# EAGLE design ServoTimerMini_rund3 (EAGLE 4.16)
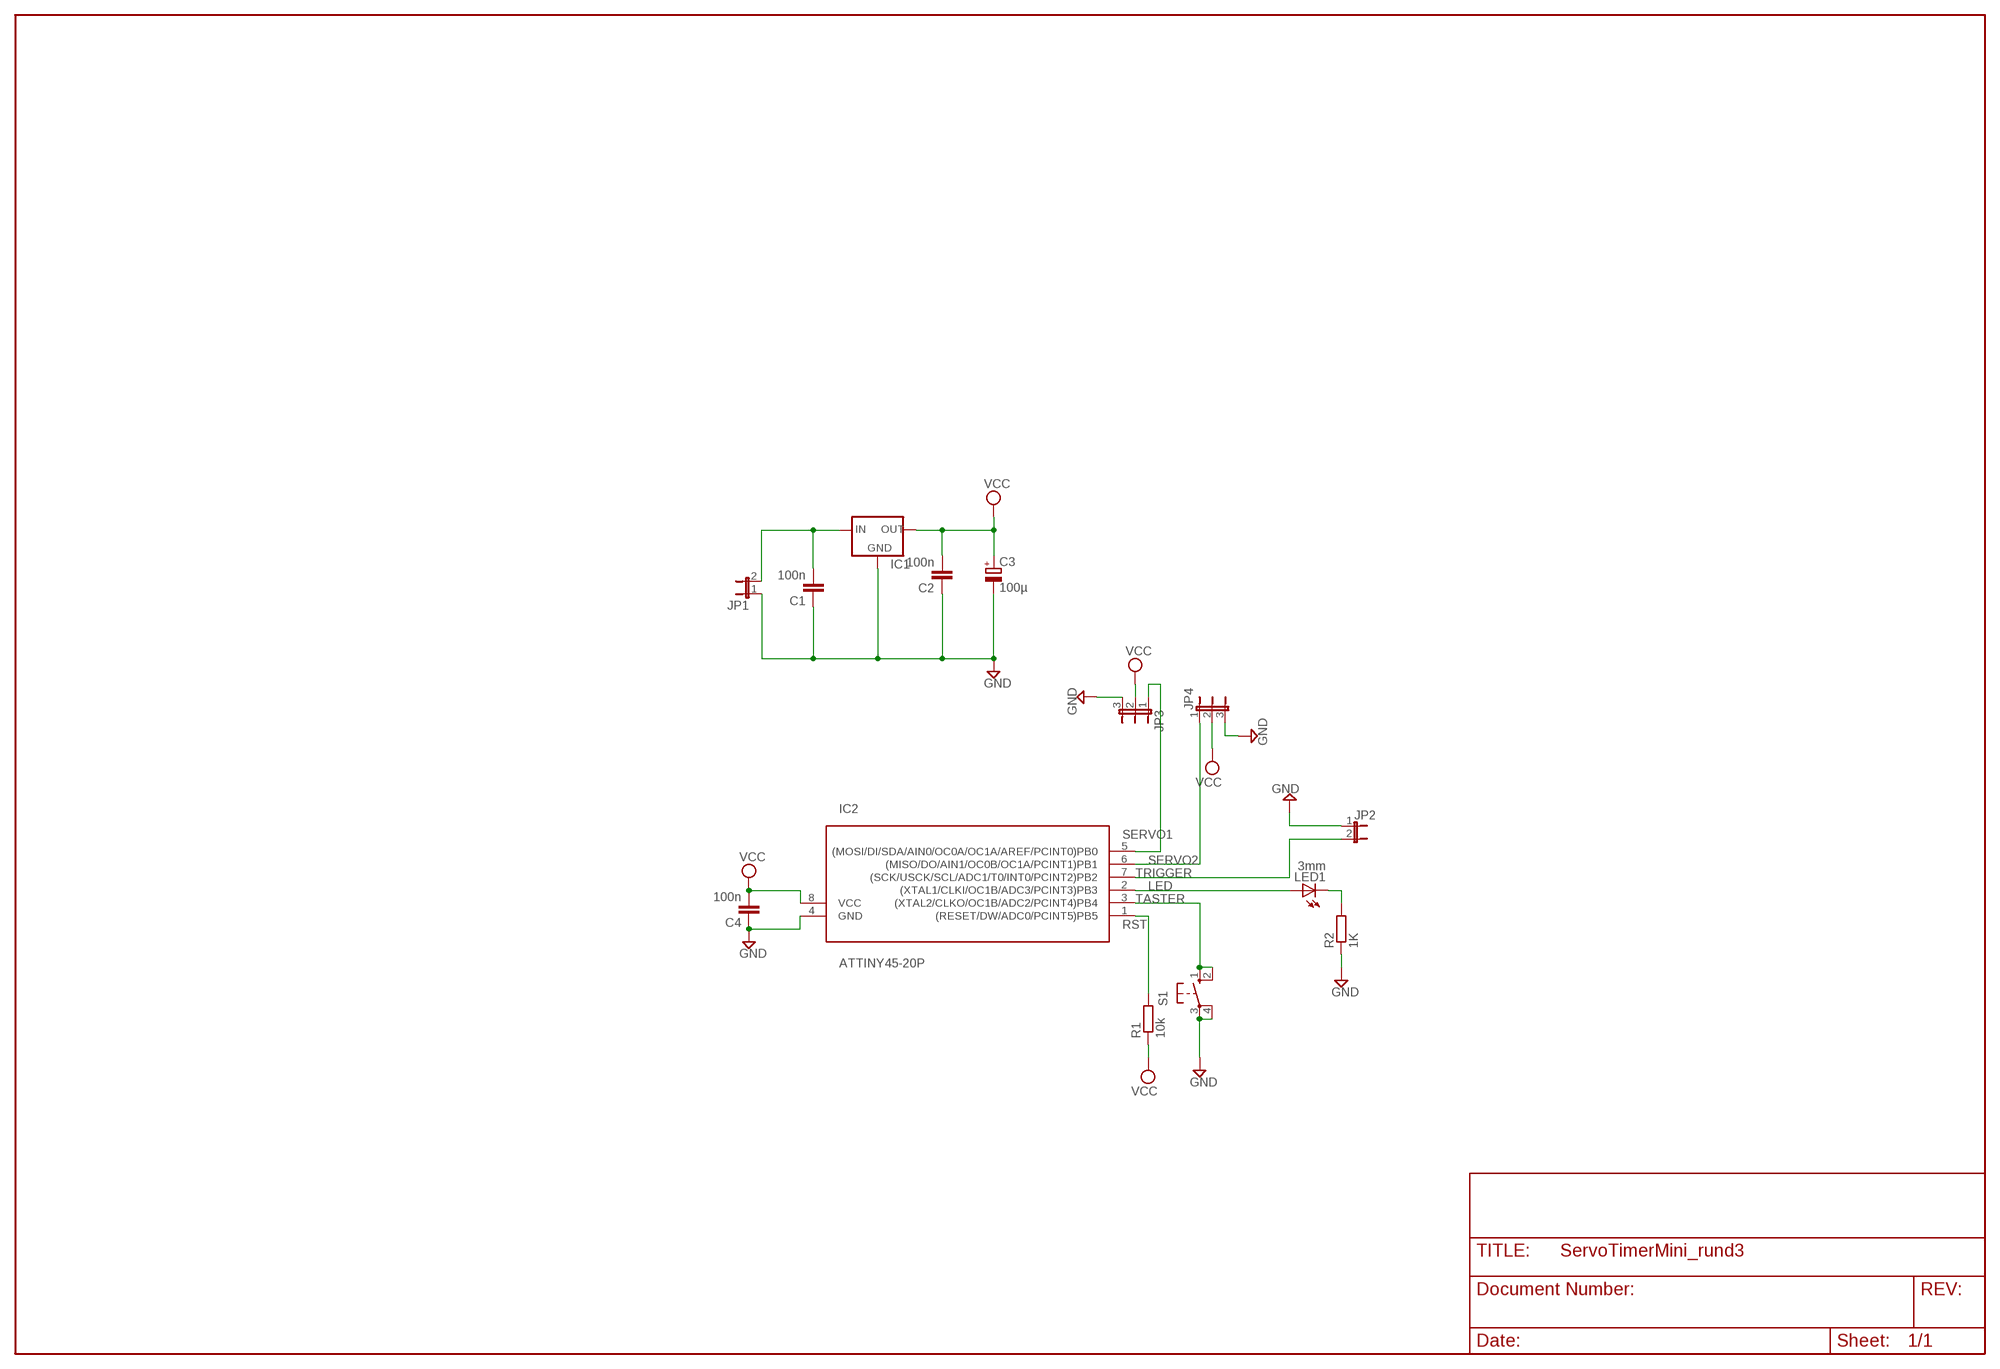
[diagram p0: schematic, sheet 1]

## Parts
C1  100n  C-EU025-025X050  [C025-025X050]
C2  100n  C-EU025-025X050  [C025-025X050]
C3  100µ  CPOL-EUE2.5-6  [E2,5-6]
C4  100n  C-EU025-025X050  [C025-025X050]
IC1  78XXL  [78XXL]
IC2  ATTINY45-20P  [DIL08]
JP1  JP1E  [JP1]
JP2  JP1E  [JP1]
JP3  JP2E  [JP2]
JP4  JP2E  [JP2]
LED1  3mm  LED3MM  [LED3MM]
R1  10k  R-EU_0204/7  [0204/7]
R2  1K  R-EU_0204/7  [0204/7]
S1  10-XX  [B3F-10XX]

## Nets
+9V: C1.2 IC1.IN JP1.2
GND: C1.1 C2.1 C3.- C4.1 IC1.GND IC2.4(GND) JP1.1 JP2.1 JP3.3 JP4.3 R2.1 S1.3(P) S1.4(P1)
LED: IC2.2((XTAL1/CLKI/OC1B/ADC3/PCINT3)PB3) LED1.A
N$4: LED1.K(C) R2.2
RST: IC2.1((RESET/DW/ADC0/PCINT5)PB5) R1.2
SERVO1: IC2.5((MOSI/DI/SDA/AIN0/OC0A/OC1A/AREF/PCINT0)PB0) JP3.1
SERVO2: IC2.6((MISO/DO/AIN1/OC0B/OC1A/PCINT1)PB1) JP4.1
TASTER: IC2.3((XTAL2/CLKO/OC1B/ADC2/PCINT4)PB4) S1.1(S) S1.2(S1)
TRIGGER: IC2.7((SCK/USCK/SCL/ADC1/T0/INT0/PCINT2)PB2) JP2.2
VCC: C2.2 C3.+ C4.2 IC1.OUT IC2.8(VCC) JP3.2 JP4.2 R1.1

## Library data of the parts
C1 C2 C4 = rcl:C-EU: CAPACITOR, European symbol
C3 = rcl:CPOL-EU: POLARIZED CAPACITOR, European symbol
IC1 = v-reg:78XXL: VOLTAGE REGULATOR
IC2 = avr:ATTINY45: MICROCONTROLLER 4 Kbytes FLASH 256 bytes EEPROM 256 bytes RAM 4-channel 10 bit ADC USI
JP1 JP2 = jumper:JP1E: JUMPER
JP3 JP4 = jumper:JP2E: JUMPER
LED1 = led:LED: LED
R1 R2 = rcl:R-EU_: RESISTOR, European symbol
S1 = switch-omron:10-XX: OMRON SWITCH

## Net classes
0 default: width 0.356 mm, drill 0.254 mm, clearance 0.61 mm
1 GND: width 0.991 mm, drill 0.254 mm, clearance 0.61 mm
2 VCC: width 0.356 mm, drill 0.254 mm, clearance 0.61 mm
3 breit2: width 2.032 mm, drill 0.483 mm, clearance 0.61 mm
4 breit3: width 2.54 mm, drill 0.61 mm, clearance 0.61 mm

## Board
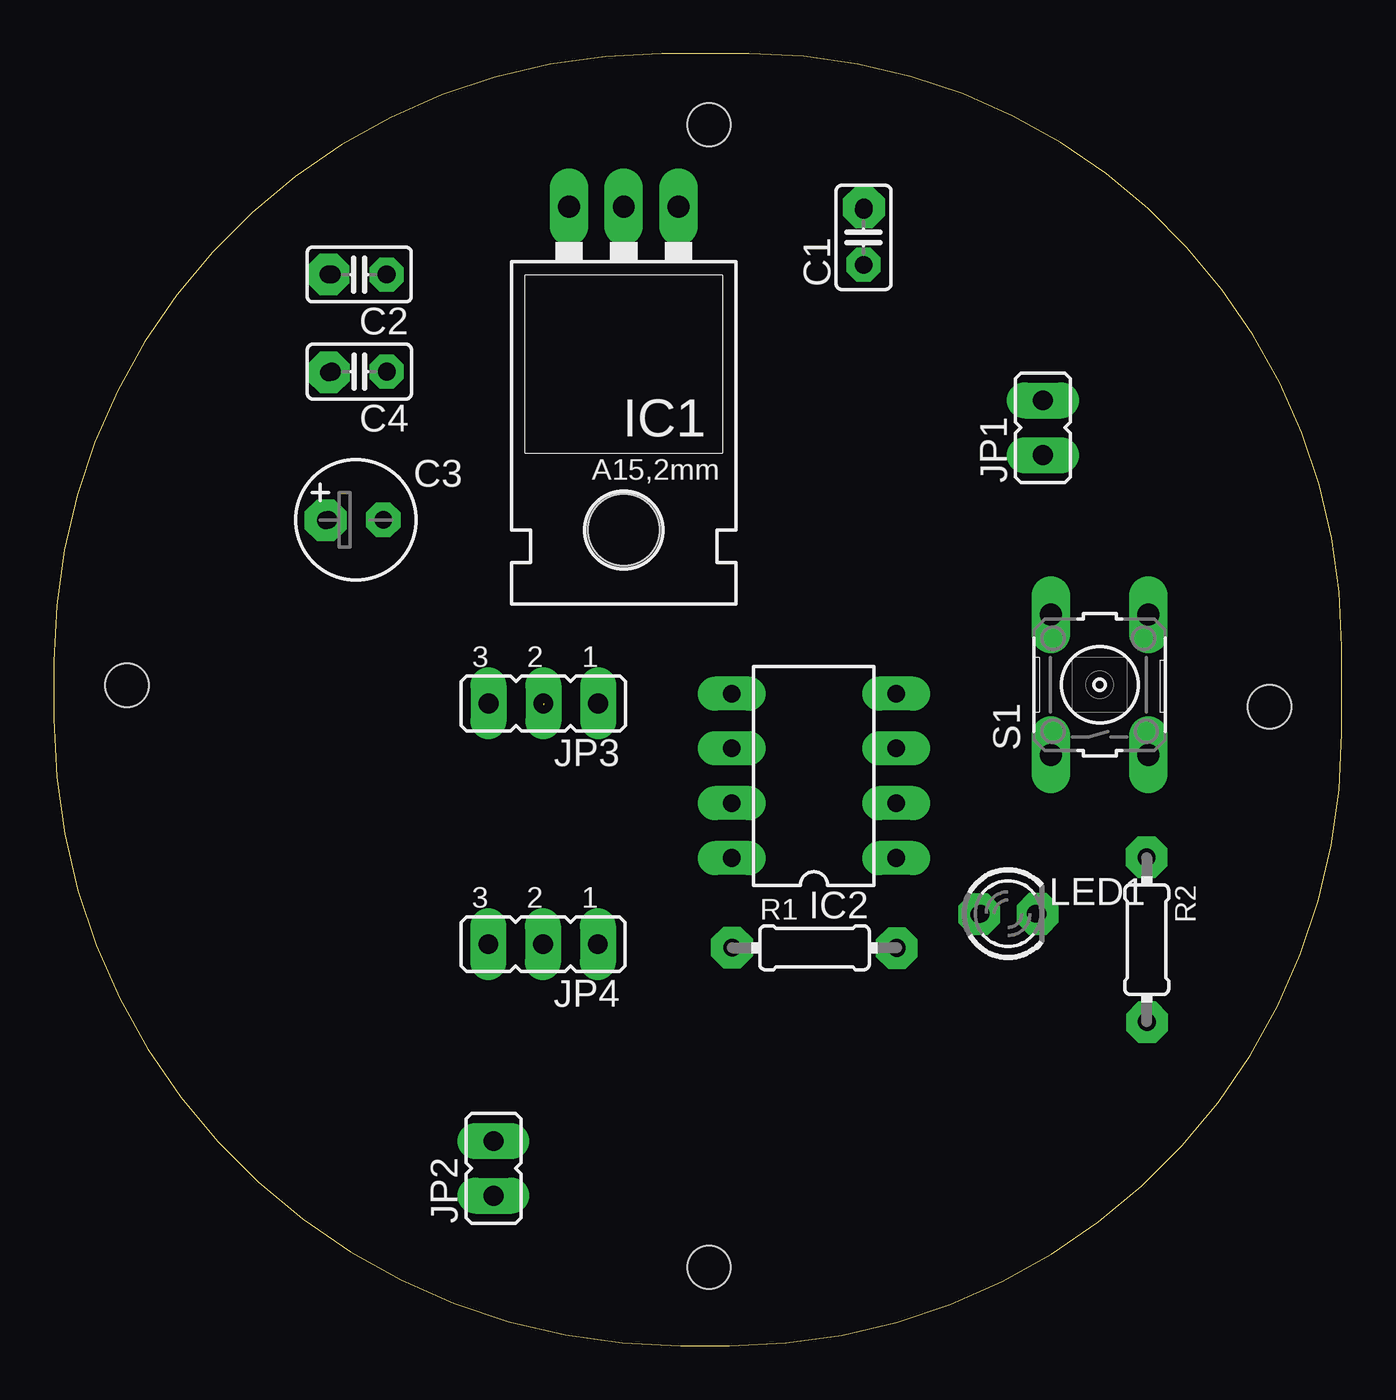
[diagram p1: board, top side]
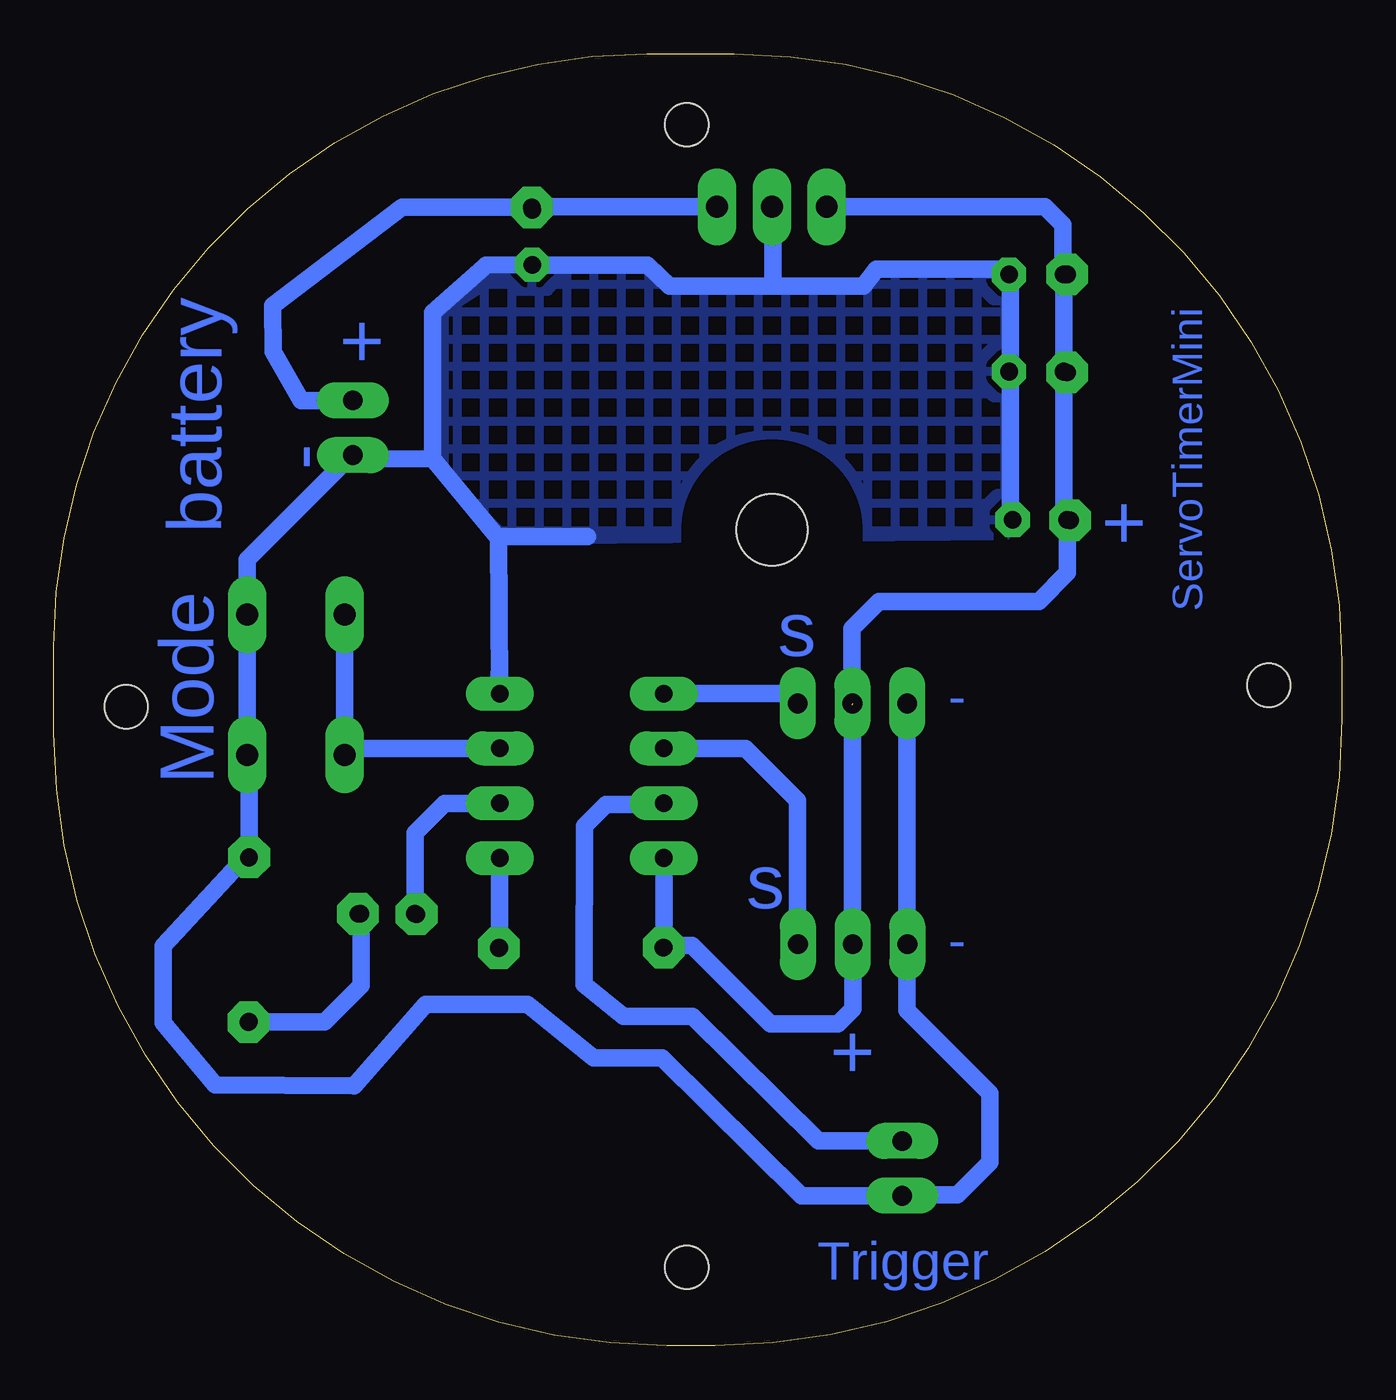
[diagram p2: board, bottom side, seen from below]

Size 59.74 x 59.91 mm. Coordinates in mm from the lower left corner, seen from the top.
Outline: 31.33,0 arc90 59.74,28.41 59.74,32.41 arc90 32.23,59.91 28.18,59.91 arc90 0,31.73 0,29.06 arc90 29.06,0 31.33,0
Copper layers (1*16): Top 0.035mm / dielectric 1.5mm / Bottom 0.035mm
Design rules "default": minimum track width 10mil, minimum drill 24mil, track to track 8mil, track to pad 8mil, pad to pad 8mil, via to via 8mil, smd to smd 8mil, copper to edge 40mil, drill to drill 8mil, minimum pad ring 15mil, minimum via ring 8mil, stop-mask expansion 4mil, vias tented up to drill 0mil, thermal gap 10mil
Holes 2 mm at 56.38,29.63 3.38,30.63 30.38,56.63 30.38,3.63

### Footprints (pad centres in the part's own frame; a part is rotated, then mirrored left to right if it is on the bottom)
C025-025X050 = drill 0.813 octagon: 1 -1.27,0; 2 1.27,0
E2,5-6 = drill 0.813 pad 1.6 round: + -1.27,0 | drill 0.813 pad 1.6 octagon: - 1.27,0
78XXL = drill 1.016 long: GND 0,-3.81; IN -2.54,-3.81; OUT 2.54,-3.81 | hole 3.302: 0,11.176
DIL08 = drill 0.813 long: 1 -3.81,-3.81; 2 -1.27,-3.81; 3 1.27,-3.81; 4 3.81,-3.81; 5 3.81,3.81; 6 1.27,3.81; 7 -1.27,3.81; 8 -3.81,3.81
JP1 = drill 0.914 long: 1 0,-1.27; 2 0,1.27
JP2 = drill 0.914 long: 1 -2.54,0; 2 0,0; 3 2.54,0
LED3MM = drill 0.813 octagon: A -1.27,0; K 1.27,0
0204/7 = drill 0.813 octagon: 1 -3.81,0; 2 3.81,0
B3F-10XX = drill 1.016 long: 1 -3.251,2.261; 2 3.251,2.261; 3 -3.251,-2.261; 4 3.251,-2.261

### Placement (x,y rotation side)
C1  37.55,51.4 90 top
C2  14.16,49.68 180 top
C3  14,38.3 0 top
C4  14.17,45.18 180 top
IC1  26.43,49.01 180 top
IC2  35.25,26.43 90 top
JP1  45.87,42.57 0 top
JP2  20.39,8.22 0 top
JP3  22.7,29.79 180 top
JP4  22.69,18.62 180 top
LED1  44.26,20.04 0 top
R1  35.28,18.45 0 top
R2  50.69,18.83 270 top
S1  48.51,30.65 90 top

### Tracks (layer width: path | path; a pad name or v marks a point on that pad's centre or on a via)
+9V
  Bottom 0.813: JP1.2 48.27,43.84 49.57,46.11 49.58,48.23 43.58,52.8 37.38,52.8 | 37.38,52.8 37.42,52.67 C1.2 37.51,52.63 37.38,52.8 | IC1.IN 37.19,52.82 37.38,52.8
GND
  Bottom 0.813: 15.3,38.3 15.38,38.19 C3.- 15.38,38.41 15.38,45.13 15.39,45.13 C4.1 15.38,45.23 15.38,49.63 C2.1 15.28,49.93 21.6,49.93 22.18,49.13 26.38,49.13 | 26.38,49.13 31.18,49.13 32.21,50.12 36.67,50.12 37.55,50.12 C1.1 39.69,50.12 39.78,50.03 42.18,47.9 42.16,41.14 | IC1.GND 26.38,52.77 26.38,49.13 | 46.88,41.13 42.16,41.14 | 39.07,30.49 39.1,37.55 34.98,37.53 39.18,37.53 42.16,41.14 | 39.07,30.49 39.12,30.9 | 46.88,41.13 JP1.1 | 46.88,41.13 45.87,41.14 JP1.1 | 46.88,41.13 45.68,41.12 | 39.07,30.49 39.08,31.19 39.06,30.68 IC2.4 | 45.87,41.36 45.76,41.47 | 45.87,41.36 JP1.1 | 45.87,41.36 50.77,36.46 S1.4 S1.3 | S1.3 50.77,27.21 50.79,27.19 | S1.3 50.77,27.33 50.69,27.26 R2.1 | 20.15,18.5 20.05,18.4 | 20.15,18.5 JP4.3 | 20.15,18.5 20.16,18.51 JP3.3 20.16,15.54 16.32,11.7 16.32,8.5 17.82,7 20.25,7 20.39,6.86 | 50.52,22.74 50.62,22.64 R2.1 | 20.39,6.86 20.45,6.8 | 20.39,6.86 JP2.1 25.07,6.96 31.52,13.33 34.7,13.33 37.76,15.83 42.5,15.83 45.81,12.05 52.25,12.08 54.66,14.96 54.66,18.55 50.86,22.64 R2.1
  pour Bottom (hatched): 38.78,37.34 41.58,40.13 41.58,48.13 39.38,49.53 36.08,50.13 31.98,50.13 31.18,49.23 22.18,49.23 21.38,50.13 15.58,50.13 15.58,37.54
LED
  Bottom 0.813: LED1.A 42.99,23.79 41.62,25.15 39.27,25.15 39.18,25.06 39.08,25.16 IC2.2
N$1  (via drill 0.8 pad 1.93)
  other vias: 37.57,52.8
N$2  (via drill 0.8 pad 1.93)
  other vias: 50.71,15
N$3  (via drill 0.8 pad 1.93)
  other vias: 42.91,20
N$4
  Bottom 0.813: 45.5,19.94 45.53,19.97 LED1.K | 45.5,19.94 45.47,19.91 | 45.5,19.94 45.5,16.71 47.18,15.02 50.68,15.02 R2.2 | R2.2 50.79,14.91 | R2.2
N$5  (via drill 0.8 pad 1.93)
  other vias: 45.63,20.02
N$6  (via drill 0.8 pad 1.93)
  other vias: 50.68,22.65
N$7  (via drill 0.8 pad 1.93)
  other vias: 39.1,18.44
N$8  (via drill 0.8 pad 1.93)
  other vias: 31.45,18.46
N$9  (via drill 0.8 pad 1.93)
  other vias: 12.75,45.13
N$10  (via drill 0.8 pad 1.93)
  other vias: 12.73,49.68
N$11  (via drill 0.8 pad 1.93)
  other vias: 12.61,38.28
RST
  Bottom 0.813: R1.2 39.01,18.45 39,18.46 39.06,18.51 IC2.1
SERVO1
  Bottom 0.813: JP3.1 25.2,29.79 25.09,29.89 25.44,30.24 IC2.5
SERVO2
  Bottom 0.813: IC2.6 27.66,27.7 25.24,25.28 25.24,18.76 25.18,18.7 25.23,18.65 JP4.1
TASTER
  Bottom 0.813: IC2.3 46.01,27.7 46.25,27.46 S1.1 46.19,27.4 | 46.19,27.4 46.1,27.31 | S1.2 46.25,27.46 46.19,27.4
TRIGGER
  Bottom 0.813: JP2.2 24.26,9.5 30.12,15.27 33.32,15.26 35.14,16.75 35.13,24.09 34.13,25.1 31.56,25.1 31.46,25.2 31.44,25.18 IC2.7
VCC  (1 unrouted)
  Bottom 0.813: IC1.OUT 13.76,52.82 12.93,51.99 12.93,49.74 12.87,49.68 | 12.87,49.68 12.81,49.62 | 12.87,49.68 C2.2 12.89,45.16 | 12.89,45.16 12.9,45.17 C4.2 12.9,38.56 12.69,38.35 C3.+ | 12.89,45.16 12.87,45.14 | C3.+ | C3.+ 12.73,35.85 14.06,34.52 21.46,34.52 22.72,33.26 22.72,29.71 22.7,29.69 | 31.54,18.45 31.64,18.35 | 31.54,18.45 R1.1 | 31.44,18.55 IC2.8 | 31.44,18.55 31.54,18.45 | 22.73,18.62 22.89,18.46 | 22.73,18.62 JP4.2 22.69,18.61 22.53,18.44 22.67,18.3 22.67,15.62 23.37,14.92 26.51,14.92 30.14,18.55 31.44,18.55 | JP3.2 22.7,18.65 22.73,18.62

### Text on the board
Bottom: battery | + | - | + | Mode | ServoTimerMini | s | - | s | - | + | Trigger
